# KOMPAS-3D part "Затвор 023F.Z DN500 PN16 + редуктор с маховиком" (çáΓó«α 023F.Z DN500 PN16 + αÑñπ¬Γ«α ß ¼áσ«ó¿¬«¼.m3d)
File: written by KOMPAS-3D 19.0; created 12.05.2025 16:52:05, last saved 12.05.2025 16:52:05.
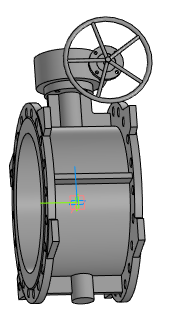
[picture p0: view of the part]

Document properties: Полное имя файла: Затвор 023F.Z DN500 PN16 + редуктор с маховиком.a3d

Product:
- Part/product: Затвор 023F.Z DN500 PN16 + редуктор с маховиком
    Масса: 314.068

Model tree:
1. Операция без истории:1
